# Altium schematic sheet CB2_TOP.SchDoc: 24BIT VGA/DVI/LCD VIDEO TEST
size A4; Engineer: SHOWELL; DocumentNumber: 1; Revision: 1.00; SheetNumber: 1; SheetTotal: 1; PageSetup: Record=PageOptions|CenterHorizontal=True|CenterVertical=True|PrintScale=1.47|XCorrection=1.00|YCorrection=1.00|PrintKind=0|BorderSize=5000000|LeftOffset=0|BottomOffset=0|Orientation=2|PaperLength=1000|PaperWidth=1000|Scale=100|PaperSource=7|PrintQuality=-4|MediaType=1|DitherType=10|PaperKind=A2|PrintScaleMode=1
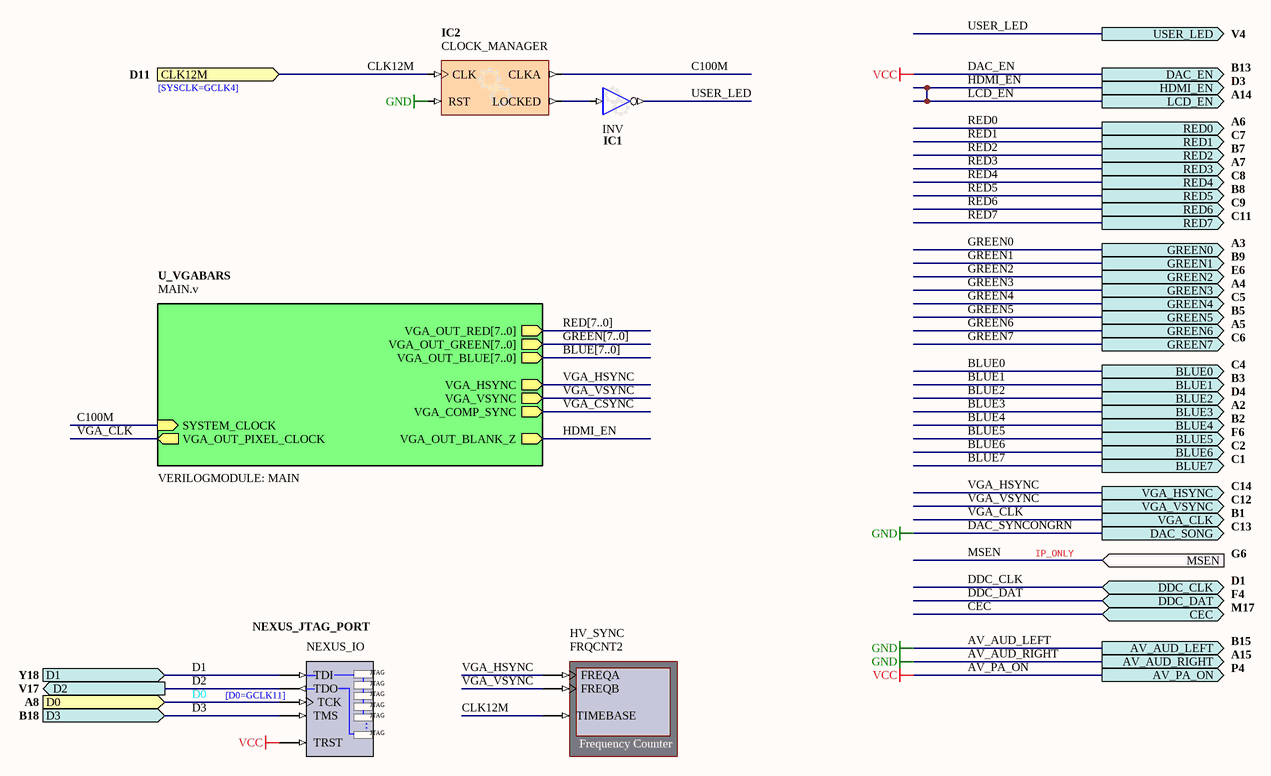
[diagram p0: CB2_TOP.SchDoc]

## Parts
HV_SYNC  FRQCNT2
IC1  INV
IC2  CLOCK_MANAGER
NEXUS_JTAG_PORT  NEXUS_IO

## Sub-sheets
U_VGABARS = MAIN.v: SYSTEM_CLOCK (in), VGA_COMP_SYNC (out), VGA_HSYNC (out), VGA_OUT_BLANK_Z (out), VGA_OUT_BLUE[7..0] (out), VGA_OUT_GREEN[7..0] (out), VGA_OUT_PIXEL_CLOCK (out), VGA_OUT_RED[7..0] (out), VGA_VSYNC (out)  | VERILOGMODULE: MAIN

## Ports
AV_AUD_LEFT (out, see B15), AV_AUD_RIGHT (out, see A15), AV_PA_ON (out, see P4), BLUE0 (out, see C4), BLUE1 (out, see B3), BLUE2 (out, see D4), BLUE3 (out, see A2), BLUE4 (out, see B2), BLUE5 (out, see F6), BLUE6 (out, see C2), BLUE7 (out, see C1), CEC (bidir, see M17), CLK12M (in, see D11), D0 (in, see A8), D1 (in, see Y18), D2 (out, see V17), D3 (in, see B18), DAC_EN (out, see B13), DAC_SONG (out, see C13), DDC_CLK (bidir, see D1), DDC_DAT (bidir, see F4), GREEN0 (out, see A3), GREEN1 (out, see B9), GREEN2 (out, see E6), GREEN3 (out, see A4), GREEN4 (out, see C5), GREEN5 (out, see B5), GREEN6 (out, see A5), GREEN7 (out, see C6), HDMI_EN (out, see D3), LCD_EN (out, see A14), MSEN (in, see G6), RED0 (out, see A6), RED1 (out, see C7), RED2 (out, see B7), RED3 (out, see A7), RED4 (out, see C8), RED5 (out, see B8), RED6 (out, see C9), RED7 (out, see C11), USER_LED (out, see V4), VGA_CLK (out, see B1), VGA_HSYNC (out, see C14), VGA_VSYNC (out, see C12)

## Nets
AV_AUD_LEFT: IC2.RST ; port DAC_SONG, port AV_AUD_LEFT, port AV_AUD_RIGHT  [also labelled AV_AUD_RIGHT, DAC_SYNCONGRN, GND]
AV_PA_ON: NEXUS_JTAG_PORT.TRST ; port AV_PA_ON, port DAC_EN  [also labelled DAC_EN, VCC]
C100M: IC2.CLKA ; sheet U_VGABARS/SYSTEM_CLOCK
CLK12M: HV_SYNC.TIMEBASE IC2.CLK ; port CLK12M
D0: NEXUS_JTAG_PORT.TCK ; port D0
D1: NEXUS_JTAG_PORT.TDI ; port D1
D2: NEXUS_JTAG_PORT.TDO ; port D2
D3: NEXUS_JTAG_PORT.TMS ; port D3
HDMI_EN: port HDMI_EN, port LCD_EN, sheet U_VGABARS/VGA_OUT_BLANK_Z  [also labelled LCD_EN]
USER_LED: IC1.O ; port USER_LED
VGA_CLK: port VGA_CLK, sheet U_VGABARS/VGA_OUT_PIXEL_CLOCK
VGA_HSYNC: HV_SYNC.FREQA ; port VGA_HSYNC, sheet U_VGABARS/VGA_HSYNC
VGA_VSYNC: HV_SYNC.FREQB ; port VGA_VSYNC, sheet U_VGABARS/VGA_VSYNC
NetIC1_I: IC1.I IC2.LOCKED

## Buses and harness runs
bus BLUE[7..0] = sheet U_VGABARS/VGA_OUT_BLUE[7..0]
bus GREEN[7..0] = sheet U_VGABARS/VGA_OUT_GREEN[7..0]
bus RED[7..0] = sheet U_VGABARS/VGA_OUT_RED[7..0]

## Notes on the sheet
- [SYSCLK=GCLK4]
- IP_ONLY
- (near NEXUS_JTAG_PORT) [D0=GCLK11]

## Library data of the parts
HV_SYNC = FRQCNT2: Frequency Counter; NEXUS_CORE: Instrument; NEXUS_JTAG_DEVICE: True; NEXUS_JTAG_ORDER: 0
IC1 = INV: Configurable Inverter; ConfiguratorName: GENERIC_BUFFER; ConfigurationParameters: {}Version[1.1]{}SignalCount[1]{}SignalWidth0[1]{}OutputOption0[Inverted]{}EnableMode[None]{}ShowPinNames[False]{}
IC2 = CLOCKMANAGER: Configurable Clock Manager; ConfiguratorName: GENERIC_CLOCKMANAGER; ConfigurationParameters: {}Version[1.0]{}Option_Configuration[object _1: TClockManagerPersist / VersionMajor [ 0 / VersionMinor [ 0 / InputFreq [ 24.000000000000000000 / InputName [ 'CLK' / OutputTargets [ < / item / Name [ 'CLKA' / OutFreqMin [ 200.000000000000000000 / OutFreqMax [ 200.000000000000000000 / OutPostDivider [ 1.000000000000000000 / end> / OutputDevices [ < / item / Name [ 'Spartan3AN' / Valid [ True / OutputActuals [ < / item / Name [ 'CLK0' / Multipler [ 1.000000000000000000 / Divider [ 1.000000000000000000 / OutFreq [ 24.000000000000000000 / OutputMap [ 1 / end / item / Name [ 'CLK90' / Multipler [ 1.000000000000000000 / Divider [ 1.000000000000000000 / OutPhase [ 90.000000000000000000 / OutFreq [ 24.000000000000000000 / OutputMap [ 2 / end / item / Name [ 'CLK180' / Multipler [ 1.000000000000000000 / Divider [ 1.000000000000000000 / OutPhase [ 180.000000000000000000 / OutFreq [ 24.000000000000000000 / OutputMap [ 3 / end / item / Name [ 'CLK270' / Multipler [ 1.000000000000000000 / Divider [ 1.000000000000000000 / OutPhase [ 270.000000000000000000 / OutFreq [ 24.000000000000000000 / OutputMap [ 4 / end / item / Name [ 'CLK2X' / Multipler [ 2.000000000000000000 / Divider [ 1.000000000000000000 / OutFreq [ 48.000000000000000000 / OutputMap [ 5 / end / item / Name [ 'CLKDV' / Multipler [ 1.000000000000000000 / Divider [ 16.000000000000000000 / OutFreq [ 1.500000000000000000 / OutputMap [ 6 / end / item / Name [ 'CLK2X180' / Multipler [ 1.000000000000000000 / Divider [ 1.000000000000000000 / OutPhase [ 180.000000000000000000 / OutFreq [ 48.000000000000000000 / OutputMap [ 7 / end / item / Name [ 'CLKFX' / Multipler [ 25.000000000000000000 / Divider [ 3.000000000000000000 / OutFreq [ 200.000000000000000000 / OutputMap [ 0 / end / item / Name [ 'CLKFX180' / Multipler [ 1.000000000000000000 / Divider [ 1.000000000000000000 / OutPhase [ 180.000000000000000000 / OutFreq [ 200.000000000000000000 / OutputMap [ 8 / end> / InternalActuals [ <> / CustomVars [ <> / end> / MinInputFreq [ 1.000000000000000000 / MaxInputFreq [ 280.000000000000000000 / MinOutputFreq [ 18.000000000000000000 / MaxOutputFreq [ 210.000000000000000000 / MaxOutputCount [ 9 / end]{}
NEXUS_JTAG_PORT = NEXUS_JTAG_PORT: Soft Nexus-Chain Connector; NEXUS_JTAG_CONNECTOR: True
